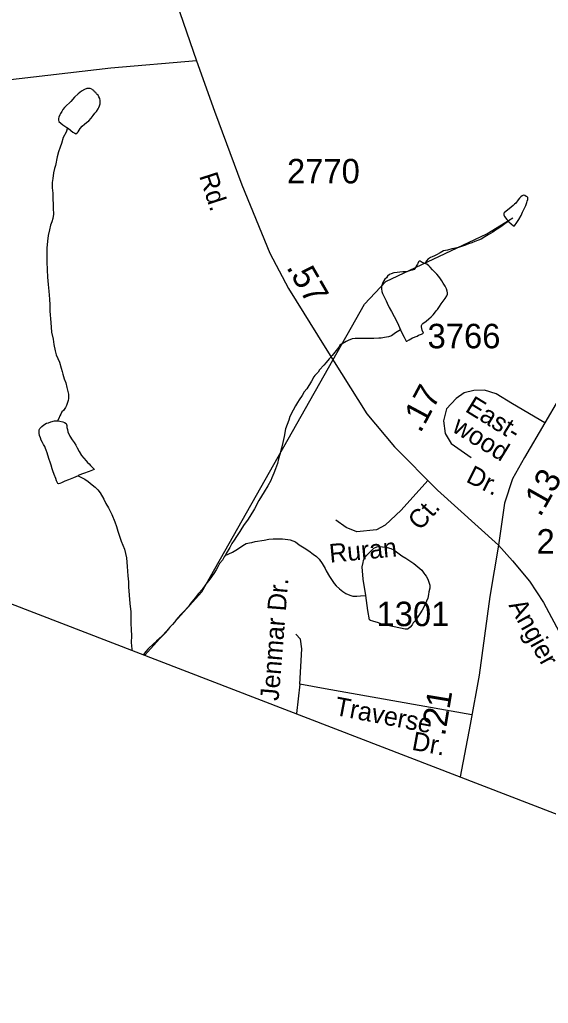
# Model space of a CAD drawing. Extents: x 2001466 to 2224147, y 644118 to 847247.
# Drawn here: x 2063498 to 2066196, y 650618 to 655639 of the extents above; entities that cross this region are included whole.
import ezdxf

# ---------------------------------------------------------------- set-up
doc = ezdxf.new("R2010")
doc.units = 0
for name, color, linetype in [('Exist Boundary Political CountyLine', 7, 'Continuous'), ('Exist Hydrographic Misc Water Feature', 7, 'Continuous'), ('Exist Road Non-System Type 51', 7, 'Continuous'), ('Exist Road Non-System Type 51 Label', 7, 'Continuous'), ('Exist Road Secondary Mileage Hundredths English Label', 7, 'Continuous'), ('Exist Road Secondary Type 41 Attributed', 7, 'Continuous'), ('Exist Road Secondary Type 51 Attributed', 7, 'Continuous'), ('Exist Road Secondary Type 51 Label', 7, 'Continuous'), ('Exist Road Secondary Type 51 Number Label', 7, 'Continuous')]:
    doc.layers.add(name, color=color, linetype=linetype)

msp = doc.modelspace()

# ---------------------------------------------------------------- linework, layer by layer
at = {"layer": 'Exist Boundary Political CountyLine'}
msp.add_lwpolyline([(2025347, 667357.1), (2026293.9, 666990.5), (2073692.9, 648709.4), (2076162.7, 647794.5), (2078580.1, 646988.2), (2083338.8, 645254.9), (2086621.1, 644117.9)], dxfattribs=at)
at = {"layer": 'Exist Hydrographic Misc Water Feature'}
for points in [[(2063742.2, 655086.6), (2063746.3, 655082.6), (2063768.4, 655064.6), (2063778.5, 655058.6), (2063784.4, 655056.6), (2063790.4, 655060.6), (2063796.3, 655066.7), (2063806.2, 655082.7), (2063816.2, 655094.7), (2063828.3, 655104.7), (2063838.4, 655114.7), (2063850.2, 655122.7), (2063862.3, 655136.7), (2063872.2, 655148.8), (2063882, 655160.8), (2063890, 655170.8), (2063898.2, 655182.8), (2063902.1, 655190.8), (2063904.2, 655198.8), (2063908.1, 655208.8), (2063908.1, 655218.8), (2063908.1, 655226.8), (2063906, 655236.8), (2063901.9, 655244.8), (2063898, 655252.8), (2063893.9, 655256.8), (2063890, 655260.8), (2063885.9, 655266.8), (2063880, 655270.7), (2063875.9, 655276.7), (2063869.9, 655280.7), (2063865.8, 655284.7), (2063857.8, 655286.7), (2063847.8, 655286.7), (2063839.8, 655286.7), (2063827.9, 655282.7), (2063813.9, 655274.6), (2063795.9, 655260.6), (2063778.1, 655242.5), (2063758, 655220.6), (2063752.2, 655214.6), (2063736, 655200.5), (2063726.2, 655190.5), (2063718.2, 655180.5), (2063712, 655170.5), (2063706.1, 655160.5), (2063702.2, 655152.4), (2063698.3, 655140.4), (2063696.2, 655134.4), (2063696.2, 655126.4), (2063698.3, 655118.4), (2063708.3, 655110.5), (2063718.2, 655102.5), (2063738.3, 655088.6), (2063742.2, 655086.6)], [(2063742.2, 655086.6), (2063734.4, 655064.6), (2063720.4, 655036.5), (2063710.4, 655006.5), (2063704.5, 654988.5), (2063696.5, 654964.5), (2063688.7, 654938.5), (2063680.7, 654894.5), (2063674.7, 654878.5), (2063670.8, 654856.5), (2063666.7, 654828.5), (2063662.8, 654808.4), (2063662.8, 654780.5), (2063666.9, 654752.5), (2063666.9, 654722.5), (2063669, 654696.5), (2063669.2, 654676.5), (2063671, 654646.5), (2063667.1, 654624.5), (2063661.2, 654606.5), (2063655.2, 654590.5), (2063649.3, 654566.5), (2063643.3, 654536.5), (2063639.5, 654508.5), (2063635.6, 654472.5), (2063635.6, 654446.5), (2063635.6, 654402.5), (2063637.6, 654362.5), (2063639.7, 654324.5), (2063643.8, 654286.5), (2063645.8, 654252.6), (2063649.9, 654212.5), (2063652, 654182.5), (2063652, 654156.5), (2063652.2, 654150.5), (2063656.1, 654092.6), (2063660.2, 654044.6), (2063668.4, 654008.6), (2063672.3, 653980.7), (2063678.4, 653948.7), (2063684.6, 653928.7), (2063692.6, 653908.7), (2063700.6, 653890.7), (2063708.6, 653860.8), (2063714.5, 653842.7), (2063718.6, 653828.7), (2063724.8, 653804.8), (2063732.7, 653784.8), (2063738.7, 653760.8), (2063746.9, 653726.9), (2063746.9, 653704.9), (2063744.8, 653694.9), (2063740.7, 653678.9), (2063737.1, 653668.8), (2063730.9, 653658.8), (2063720.9, 653644.8)], [(2065992.6, 654610.8), (2065994.7, 654606.9), (2066006.8, 654596.9), (2066018.7, 654586.9), (2066022.8, 654586.9), (2066034.7, 654603), (2066044.7, 654619), (2066056.6, 654639), (2066064.6, 654657), (2066070.5, 654669), (2066080.4, 654691.1), (2066086.5, 654705.1), (2066088.4, 654713.1), (2066090.4, 654721), (2066090.4, 654725), (2066090.4, 654731), (2066088.4, 654735), (2066082.4, 654737), (2066076.5, 654741), (2066068.5, 654743), (2066062.6, 654739), (2066054.6, 654735), (2066048.4, 654727), (2066042.5, 654718.9), (2066030.6, 654702.9), (2066022.6, 654696.9), (2066016.6, 654690.9), (2065996.5, 654672.9), (2065980.5, 654660.9), (2065970.7, 654652.9), (2065968.6, 654648.9), (2065968.6, 654642.8), (2065972.5, 654634.8), (2065984.6, 654618.8), (2065992.6, 654610.8)], [(2064136.2, 652395.3), (2064427.9, 652717.7), (2065257.9, 654187.1), (2065365.8, 654302.9), (2065881.9, 654545.1), (2066014.8, 654627.7)], [(2065992.6, 654610.8), (2065960.6, 654586.8), (2065942.8, 654574.8), (2065926.8, 654564.8), (2065912.9, 654554.7), (2065888.9, 654540.7), (2065870.8, 654530.7), (2065852.8, 654518.7), (2065838.8, 654512.6), (2065821, 654506.6), (2065805, 654500.5), (2065789, 654494.5), (2065773, 654488.5), (2065736.9, 654476.4), (2065712.9, 654470.4), (2065702.9, 654468.3), (2065680.9, 654462.3), (2065661.1, 654458.3)], [(2065661.1, 654458.3), (2065643, 654448.3), (2065625.2, 654438.2), (2065615.1, 654434.2), (2065603, 654428.2), (2065595, 654424.1), (2065589.1, 654422.1), (2065583.1, 654418.1), (2065573.1, 654408.1), (2065565.3, 654394.1)], [(2065565.3, 654394.1), (2065551.2, 654400.1), (2065541.3, 654406.1), (2065537.2, 654406.1), (2065533.3, 654402.1), (2065529.2, 654394), (2065527.2, 654390), (2065521.2, 654380), (2065515.3, 654370), (2065511.2, 654364), (2065501.1, 654360), (2065487.2, 654356), (2065477.1, 654354), (2065467.3, 654352), (2065453.3, 654351.9), (2065437.3, 654349.9), (2065423.4, 654347.9), (2065407.4, 654345.9), (2065393.3, 654341.9), (2065385.3, 654337.8), (2065375.4, 654329.8), (2065369.3, 654321.8), (2065361.3, 654313.8), (2065355.3, 654305.8), (2065351.4, 654297.7), (2065347.5, 654287.7), (2065343.4, 654277.7), (2065343.4, 654265.7), (2065345.5, 654251.7), (2065349.4, 654241.8), (2065351.4, 654237.8)], [(2065441.9, 654056), (2065451.9, 654034), (2065459.9, 654018), (2065466.1, 654004), (2065470, 653998), (2065474.1, 653998), (2065485.9, 654004), (2065501.7, 654014.1), (2065525.9, 654024.1), (2065533.9, 654028.1), (2065547.9, 654034.1), (2065557.9, 654038.2), (2065551.8, 654054.2), (2065547.9, 654070.2), (2065547.7, 654078.2), (2065551.8, 654084.2), (2065555.7, 654088.2), (2065571.7, 654100.2), (2065585.8, 654112.2), (2065597.7, 654122.2), (2065607.7, 654132.3), (2065615.5, 654140.3), (2065623.5, 654152.3), (2065629.5, 654160.3), (2065639.5, 654174.3), (2065649.6, 654188.3), (2065659.4, 654202.3), (2065669.5, 654216.4), (2065677.5, 654228.4), (2065681.4, 654238.4), (2065681.4, 654244.4), (2065679.5, 654252.4), (2065675.4, 654264.3), (2065669.3, 654278.3), (2065659.4, 654294.3), (2065651.4, 654306.3), (2065645.3, 654316.3), (2065637.3, 654328.3), (2065627.2, 654340.3), (2065615.1, 654352.2), (2065605.3, 654362.2), (2065593.2, 654376.2), (2065585.2, 654382.2), (2065575.1, 654390.1), (2065565.3, 654394.1)], [(2065351.4, 654237.8), (2065355.5, 654227.7), (2065361.7, 654217.7), (2065367.6, 654203.8), (2065373.6, 654191.8), (2065383.6, 654169.8), (2065395.7, 654149.8), (2065409.7, 654123.9), (2065425.7, 654091.9), (2065441.9, 654056)], [(2065441.9, 654056), (2065415.8, 654039.9), (2065395.9, 654025.9), (2065379.9, 654019.8), (2065369.9, 654017.8), (2065360, 654015.8), (2065342, 654013.8), (2065329.9, 654013.8), (2065305.9, 654011.7), (2065292, 654011.7), (2065278, 654011.6), (2065268, 654011.6), (2065257.9, 654011.6), (2065239.9, 654011.6), (2065220, 654011.6), (2065209.9, 654011.5), (2065194, 654009.5), (2065173.9, 654001.5), (2065164, 653995.5), (2065132, 653977.4)], [(2065132, 653977.4), (2065126.1, 653967.4), (2065106, 653941.3), (2065092, 653925.3), (2065076.3, 653907.4), (2065062.1, 653889.3), (2065050.2, 653875.3), (2065028.3, 653851.2), (2065020.3, 653839.2), (2065008.4, 653827.2), (2065004.3, 653823.2), (2064998.3, 653815.2)], [(2064998.3, 653815.2), (2064986.4, 653793.1), (2064962.4, 653755.2), (2064950.3, 653739.1), (2064938.7, 653721.1), (2064924.5, 653699.1), (2064914.7, 653685.1), (2064904.6, 653667), (2064892.7, 653645), (2064876.7, 653613), (2064870.8, 653595), (2064862.8, 653573), (2064854.8, 653551), (2064847, 653510.9), (2064841.1, 653480.9), (2064833.1, 653451), (2064825.1, 653419), (2064819.1, 653396.9), (2064813.2, 653372.9), (2064803.3, 653346.9), (2064795.3, 653324.9), (2064785.3, 653300.9), (2064779.3, 653286.9), (2064763.3, 653258.8), (2064745.5, 653228.8), (2064717.6, 653184.7), (2064695.7, 653142.8), (2064671.7, 653102.7), (2064659.8, 653084.7), (2064643.8, 653062.7), (2064631.9, 653042.6), (2064621.9, 653026.7), (2064604, 653000.6), (2064591.9, 652982.6), (2064580, 652964.6), (2064570, 652944.6), (2064552.1, 652914.5), (2064546.2, 652904.5)], [(2063720.9, 653644.8), (2063712.9, 653636.8), (2063706.9, 653624.8), (2063703, 653616.8), (2063697.1, 653602.8), (2063691.1, 653590.8)], [(2063795.5, 653311), (2063771.5, 653301), (2063747.5, 653290.9), (2063727.6, 653282.9), (2063711.6, 653274.9), (2063701.8, 653270.9), (2063695.6, 653268.9), (2063691.7, 653270.8), (2063685.6, 653284.8), (2063681.5, 653296.8), (2063673.5, 653316.8), (2063667.5, 653336.8), (2063663.4, 653346.7), (2063657.5, 653364.7), (2063653.4, 653380.7), (2063647.4, 653394.7), (2063641.3, 653416.7), (2063637.4, 653428.7), (2063633.3, 653440.7), (2063629.4, 653450.6), (2063625.3, 653460.6), (2063619.4, 653470.6), (2063613.4, 653480.6), (2063607.3, 653492.6), (2063603.2, 653504.6), (2063599.3, 653516.6), (2063597.2, 653528.6), (2063597.2, 653534.6), (2063597.2, 653544.6), (2063601.1, 653552.6), (2063611.2, 653562.6), (2063621, 653570.6), (2063635.1, 653578.7), (2063645, 653580.7), (2063657.1, 653586.7), (2063675.1, 653590.8), (2063691.1, 653590.8)], [(2063691.1, 653590.8), (2063703, 653588.8), (2063717.2, 653586.8), (2063727, 653582.8), (2063735, 653576.9), (2063739.1, 653566.9), (2063739.1, 653556.9), (2063741.2, 653546.9), (2063743.2, 653534.9), (2063753.3, 653512.9), (2063765.1, 653494.9), (2063775.2, 653480.9), (2063783.4, 653467), (2063791.4, 653453), (2063801.2, 653435), (2063813.3, 653415), (2063825.2, 653401), (2063837.5, 653387), (2063843.5, 653379.1), (2063851.5, 653371.1), (2063859.5, 653363.1), (2063869.5, 653353.1), (2063875.5, 653347.1), (2063877.5, 653343.2), (2063851.5, 653333.1), (2063823.6, 653323.1), (2063799.6, 653313.1), (2063795.5, 653311)], [(2063795.5, 653311), (2063829.5, 653293.1), (2063847.6, 653281.1), (2063867.5, 653265.2), (2063883.7, 653253.2), (2063895.8, 653239.2), (2063907.7, 653223.2), (2063927.8, 653191.3), (2063937.8, 653169.3), (2063951.7, 653147.4), (2063967.7, 653113.3), (2063983.9, 653075.4), (2063991.9, 653051.4), (2063998.1, 653027.4), (2064006.1, 653007.5), (2064016.1, 652977.5), (2064024.1, 652957.5), (2064032.1, 652935.6), (2064038.3, 652913.6), (2064042.4, 652891.6), (2064044.2, 652869.5), (2064046.3, 652847.5), (2064048.5, 652823.6), (2064050.4, 652799.6), (2064052.4, 652769.6), (2064052.6, 652743.6), (2064056.5, 652701.6), (2064060.6, 652659.7), (2064064.7, 652615.7), (2064064.7, 652587.7), (2064064.9, 652557.7), (2064067, 652525.7), (2064069, 652493.7), (2064067, 652459.7), (2064069.2, 652425.7), (2064069.6, 652421)], [(2064546.2, 652904.5), (2064584.1, 652920.6), (2064600.1, 652930.6), (2064620, 652942.6), (2064636, 652954.7), (2064654, 652964.7), (2064669.8, 652968.8), (2064681.9, 652970.8), (2064700, 652974.8), (2064711.9, 652976.8), (2064734, 652980.9), (2064745.9, 652982.9), (2064769.9, 652986.9), (2064791.8, 652988.9), (2064811.9, 652989), (2064839.8, 652989.1), (2064865.9, 652985.1), (2064878, 652983.1), (2064905.9, 652973.2), (2064923.9, 652959.2), (2064949.9, 652943.2), (2064974.1, 652927.3), (2064996.1, 652911.4), (2065012.1, 652899.4), (2065026, 652885.5), (2065042, 652863.4), (2065056.2, 652837.5), (2065062.1, 652825.5), (2065078.1, 652797.5), (2065092.2, 652775.6), (2065102.3, 652761.6), (2065112.3, 652749.6), (2065130.4, 652733.6), (2065146.4, 652719.7), (2065162.4, 652709.7), (2065182.5, 652701.7), (2065198.5, 652695.8), (2065218.4, 652695.9), (2065236.4, 652697.9), (2065264.3, 652699.9)], [(2064546.2, 652904.5), (2064542.1, 652896.5), (2064532.2, 652880.5), (2064518.1, 652862.5), (2064508.3, 652846.5), (2064500.3, 652830.4), (2064488.4, 652812.4), (2064468.5, 652782.4), (2064448.4, 652758.4), (2064428.5, 652730.3), (2064410.4, 652710.3), (2064392.6, 652688.3), (2064368.6, 652658.2), (2064358.8, 652644.2), (2064334.6, 652618.2), (2064320.6, 652602.1), (2064304.8, 652586.1), (2064296.8, 652576.1), (2064288.9, 652566.1), (2064276.8, 652552.1), (2064263, 652536.1), (2064255, 652524.1), (2064238.8, 652506), (2064222.8, 652490), (2064209.1, 652478), (2064195.1, 652465.9), (2064181, 652453.9), (2064153.1, 652427.8), (2064141.2, 652413.9), (2064129, 652398.1)], [(2065264.3, 652699.9), (2065250.1, 652783.9), (2065246, 652845.8), (2065250.1, 652867.8), (2065252, 652877.8), (2065258.1, 652889.8), (2065265.9, 652901.9), (2065278, 652913.9), (2065286, 652921.9), (2065297.9, 652933.9), (2065305.9, 652942), (2065319.9, 652948), (2065334, 652950), (2065350, 652948), (2065374, 652944.1), (2065391.8, 652940.1), (2065407.8, 652932.2), (2065427.9, 652918.1), (2065448, 652902.2), (2065467.9, 652890.3), (2065510.1, 652862.4), (2065530, 652846.4), (2065550.1, 652828.4), (2065560, 652814.5), (2065566.1, 652806.5), (2065572.1, 652798.5), (2065580.1, 652782.5), (2065586.2, 652768.5), (2065590.1, 652752.5), (2065590.1, 652736.6), (2065586.2, 652718.5), (2065584.4, 652704.5), (2065580.3, 652686.5), (2065574.3, 652670.5), (2065566.3, 652654.5), (2065552.4, 652624.4), (2065540.5, 652606.4), (2065530.4, 652590.5), (2065518.5, 652572.4), (2065506.4, 652560.4), (2065500.5, 652550.4), (2065490.5, 652538.4), (2065480.6, 652530.3), (2065476.7, 652528.3), (2065464.6, 652528.3), (2065376.7, 652546.2), (2065348.6, 652552.1), (2065328.5, 652560.1), (2065300.6, 652568), (2065288.5, 652572), (2065282.5, 652575.9), (2065274.5, 652624), (2065264.3, 652699.9)]]:
    msp.add_lwpolyline(points, dxfattribs=at)
at = {"layer": 'Exist Road Non-System Type 51'}
for points in [[(2065581.1, 653287.4), (2065444.5, 653135.7), (2065362.6, 653058.5), (2065319.2, 653034.4), (2065217.9, 653024.8), (2065164.4, 653047.2), (2065110.9, 653084.7)], [(2064927.9, 652247.6), (2064938.5, 652428.1), (2064930.5, 652476.2), (2064906.5, 652503)], [(2064927.9, 652247.6), (2064909.7, 652097)], [(2065805.1, 652091), (2065056.1, 652223.5), (2064927.9, 652247.6)]]:
    msp.add_lwpolyline(points, dxfattribs=at)
at = {"layer": 'Exist Road Secondary Type 41 Attributed'}
msp.add_lwpolyline([(2064400.8, 655428.7), (2063962.2, 655391.7), (2063421.8, 655328.3), (2063058.7, 655290.3), (2063003.8, 655281.9), (2062927.8, 655235.4), (2062881.4, 655172), (2062834.9, 655049.5), (2062729.4, 654796), (2062628, 654542.5), (2062514, 654327), (2062418, 654168.5), (2062092.9, 653803.1), (2061951.4, 653657.3), (2061765.6, 653484.1), (2061613.7, 653368.2)], dxfattribs=at)
at = {"layer": 'Exist Road Secondary Type 51 Attributed'}
for points in [[(2063511.5, 657876.1), (2063619.2, 657582.5), (2063752.2, 657212.8), (2064004.5, 656526.2), (2064154.3, 656103.7), (2064315.8, 655674.8), (2064400.8, 655428.7)], [(2064400.8, 655428.7), (2064492.6, 655171), (2064632, 654794.9), (2064774.5, 654446.3), (2064869.5, 654266.8), (2065057.4, 653964.7), (2065269.5, 653626.7), (2065411, 653457.7), (2065630.5, 653238), (2065941.4, 652955.9)], [(2066501.6, 654994.4), (2066476.5, 654724.2), (2066435.9, 654338.6), (2066409, 654058.7), (2066394.2, 654002.7), (2066368.9, 653920.3), (2066317.2, 653820), (2066178.3, 653581.2)], [(2066178.3, 653581.2), (2066013.2, 653677.4), (2065928.7, 653729.1), (2065869.6, 653747.1), (2065814.7, 653746), (2065766.2, 653733.4), (2065726, 653704.8), (2065676.4, 653653.1), (2065660.6, 653591.8), (2065669, 653527.4), (2065699.7, 653475.6), (2065802, 653404.8)], [(2066178.3, 653581.2), (2066074.4, 653403.8), (2066013.2, 653295), (2065972.5, 653171.4), (2065941.4, 652955.9)], [(2065941.4, 652955.9), (2065897, 652695), (2065842.2, 652293.6), (2065796.2, 652042.2), (2065745.3, 651774.7)], [(2065941.4, 652955.9), (2066013.2, 652876.7), (2066099.7, 652773.2), (2066171.5, 652663.3), (2066264.4, 652488), (2066346.7, 652247.2), (2066489.7, 651761.6)]]:
    msp.add_lwpolyline(points, dxfattribs=at)

# ---------------------------------------------------------------- texts
at = {"layer": 'Exist Road Non-System Type 51 Label'}
for s, rotation, p in [('Ct.', 48.0077, (2065540.6, 653026.9)), ('Ruran', 5.4428, (2065081.7, 652866.9)), ('Jenmar Dr.', 85.3667, (2064818.8, 652159.9)), ('Traverse', 349.1393, (2065100.6, 652090.6)), ('Dr.', 349.5791, (2065494.9, 651912.9))]:
    msp.add_text(s, height=95, rotation=rotation, dxfattribs=at).set_placement(p)
at = {"layer": 'Exist Road Secondary Mileage Hundredths English Label'}
for s, rotation, p in [('.57', 299.9137, (2064856.5, 654375.2)), ('.17', 61.792, (2065542.5, 653524.8)), ('.13', 60.6334, (2066154.3, 653096.4)), ('.21', 80.519, (2065667.9, 651978.8))]:
    msp.add_text(s, height=125, rotation=rotation, dxfattribs=at).set_placement(p)
at = {"layer": 'Exist Road Secondary Type 51 Label'}
for s, rotation, p in [('Rd.', 287.8304, (2064413.1, 654841.5)), ('East-', 328.3804, (2065766, 653642)), ('wood', 328.3804, (2065699, 653540)), ('Dr.', 333.4256, (2065770.2, 653282.4)), ('Angier', 298.9759, (2065991.1, 652650))]:
    msp.add_text(s, height=95, rotation=rotation, dxfattribs=at).set_placement(p)
at = {"layer": 'Exist Road Secondary Type 51 Number Label'}
for s, p in [('2770', (2064861.9, 654803.1)), ('3766', (2065579.3, 653961.4)), ('2770', (2066135.6, 652913.5)), ('1301', (2065318.8, 652543.3))]:
    msp.add_text(s, height=125, dxfattribs=at).set_placement(p)

doc.saveas('drawing.dxf')
